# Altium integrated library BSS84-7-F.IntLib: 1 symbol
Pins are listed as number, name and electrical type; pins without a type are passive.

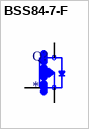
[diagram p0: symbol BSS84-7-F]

## BSS84-7-F
designator Q?
MOSFET P-Channel 50V 0.13A SOT23 ¦ Diodes Inc BSS84-7-F; MF: Diodes Inc.
footprint SOT23-R
pins: 1 G, 2 S, 3 D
